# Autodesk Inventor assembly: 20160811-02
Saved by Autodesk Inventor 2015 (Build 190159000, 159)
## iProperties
Created: 2016-08
Part Number: 20160811-02
Document SubType Name: Assembly
Designer: navara
Author: navara
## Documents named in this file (3)
- D:\20160811\20160811-02.iam
- D:\20160811\20160811-02.ipt
- D:\20160811\20160811-03.ipt
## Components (3 placed, 2 different names)
1. 20160811-02:1
2. 20160811-02:2
3. 20160811-03:1
